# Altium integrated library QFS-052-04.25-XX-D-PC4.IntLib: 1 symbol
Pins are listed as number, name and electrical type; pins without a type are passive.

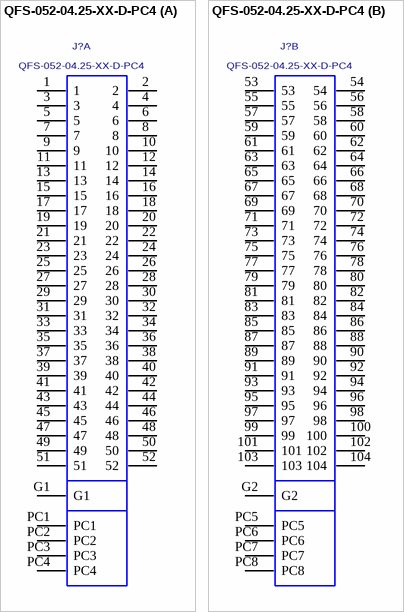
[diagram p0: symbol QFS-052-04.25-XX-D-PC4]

## QFS-052-04.25-XX-D-PC4
designator J?
0.635MM DOUBLE ROW TERMINAL STRIP.; MANUFACTURER: SAMTEC
footprint QFS-052-04.25-XX-D-PC4
part A pins: 1, 2, 3, 4, 5, 6, 7, 8, 9, 10, 11, 12, 13, 14, 15, 16, 17, 18, 19, 20, 21, 22, 23, 24, 25, 26, 27, 28, 29, 30, 31, 32, 33, 34, 35, 36, 37, 38, 39, 40, 41, 42, 43, 44, 45, 46, 47, 48, 49, 50, 51, 52, G1, PC1, PC2, PC3, PC4
part B pins: 53, 54, 55, 56, 57, 58, 59, 60, 61, 62, 63, 64, 65, 66, 67, 68, 69, 70, 71, 72, 73, 74, 75, 76, 77, 78, 79, 80, 81, 82, 83, 84, 85, 86, 87, 88, 89, 90, 91, 92, 93, 94, 95, 96, 97, 98, 99, 100, 101, 102, 103, 104, G2, PC5, PC6, PC7, PC8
